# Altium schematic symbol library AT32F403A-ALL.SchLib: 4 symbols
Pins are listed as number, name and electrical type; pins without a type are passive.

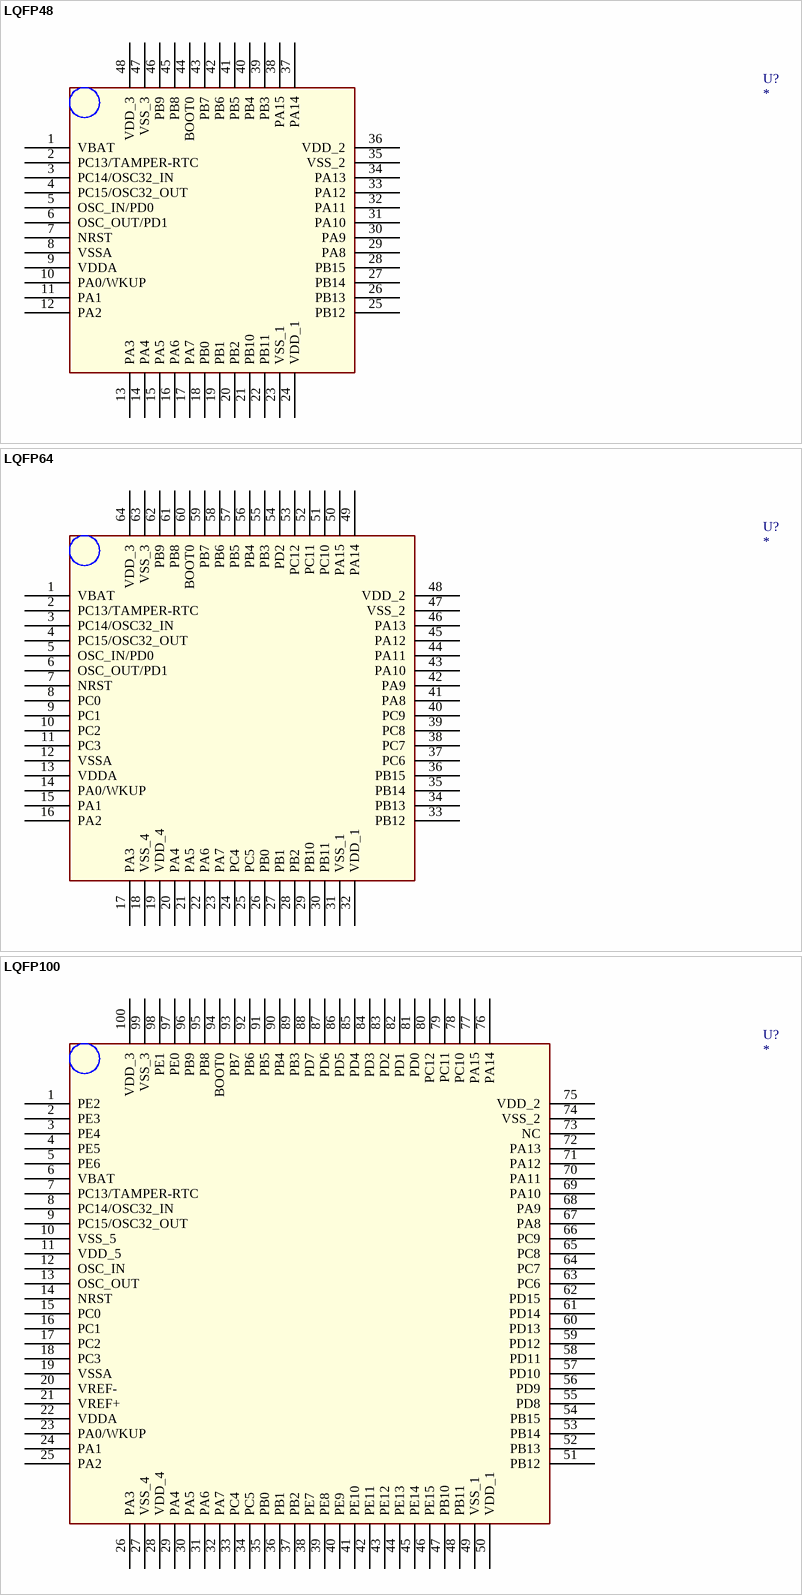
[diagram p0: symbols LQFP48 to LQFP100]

## LQFP48
designator U?
pins: 1 VBAT, 2 PC13/TAMPER-RTC, 3 PC14/OSC32_IN, 4 PC15/OSC32_OUT, 5 OSC_IN/PD0, 6 OSC_OUT/PD1, 7 NRST, 8 VSSA, 9 VDDA, 10 PA0/WKUP, 11 PA1, 12 PA2, 13 PA3, 14 PA4, 15 PA5, 16 PA6, 17 PA7, 18 PB0, 19 PB1, 20 PB2, 21 PB10, 22 PB11, 23 VSS_1, 24 VDD_1, 25 PB12, 26 PB13, 27 PB14, 28 PB15, 29 PA8, 30 PA9, 31 PA10, 32 PA11, 33 PA12, 34 PA13, 35 VSS_2, 36 VDD_2, 37 PA14, 38 PA15, 39 PB3, 40 PB4, 41 PB5, 42 PB6, 43 PB7, 44 BOOT0, 45 PB8, 46 PB9, 47 VSS_3, 48 VDD_3

## LQFP64
designator U?
pins: 1 VBAT, 2 PC13/TAMPER-RTC, 3 PC14/OSC32_IN, 4 PC15/OSC32_OUT, 5 OSC_IN/PD0, 6 OSC_OUT/PD1, 7 NRST, 8 PC0, 9 PC1, 10 PC2, 11 PC3, 12 VSSA, 13 VDDA, 14 PA0/WKUP, 15 PA1, 16 PA2, 17 PA3, 18 VSS_4, 19 VDD_4, 20 PA4, 21 PA5, 22 PA6, 23 PA7, 24 PC4, 25 PC5, 26 PB0, 27 PB1, 28 PB2, 29 PB10, 30 PB11, 31 VSS_1, 32 VDD_1, 33 PB12, 34 PB13, 35 PB14, 36 PB15, 37 PC6, 38 PC7, 39 PC8, 40 PC9, 41 PA8, 42 PA9, 43 PA10, 44 PA11, 45 PA12, 46 PA13, 47 VSS_2, 48 VDD_2, 49 PA14, 50 PA15, 51 PC10, 52 PC11, 53 PC12, 54 PD2, 55 PB3, 56 PB4, 57 PB5, 58 PB6, 59 PB7, 60 BOOT0, 61 PB8, 62 PB9, 63 VSS_3, 64 VDD_3

## LQFP100
designator U?
pins: 1 PE2, 2 PE3, 3 PE4, 4 PE5, 5 PE6, 6 VBAT, 7 PC13/TAMPER-RTC, 8 PC14/OSC32_IN, 9 PC15/OSC32_OUT, 10 VSS_5, 11 VDD_5, 12 OSC_IN, 13 OSC_OUT, 14 NRST, 15 PC0, 16 PC1, 17 PC2, 18 PC3, 19 VSSA, 20 VREF-, 21 VREF+, 22 VDDA, 23 PA0/WKUP, 24 PA1, 25 PA2, 26 PA3, 27 VSS_4, 28 VDD_4, 29 PA4, 30 PA5, 31 PA6, 32 PA7, 33 PC4, 34 PC5, 35 PB0, 36 PB1, 37 PB2, 38 PE7, 39 PE8, 40 PE9, 41 PE10, 42 PE11, 43 PE12, 44 PE13, 45 PE14, 46 PE15, 47 PB10, 48 PB11, 49 VSS_1, 50 VDD_1, 51 PB12, 52 PB13, 53 PB14, 54 PB15, 55 PD8, 56 PD9, 57 PD10, 58 PD11, 59 PD12, 60 PD13, 61 PD14, 62 PD15, 63 PC6, 64 PC7, 65 PC8, 66 PC9, 67 PA8, 68 PA9, 69 PA10, 70 PA11, 71 PA12, 72 PA13, 73 NC, 74 VSS_2, 75 VDD_2, 76 PA14, 77 PA15, 78 PC10, 79 PC11, 80 PC12, 81 PD0, 82 PD1, 83 PD2, 84 PD3, 85 PD4, 86 PD5, 87 PD6, 88 PD7, 89 PB3, 90 PB4, 91 PB5, 92 PB6, 93 PB7, 94 BOOT0, 95 PB8, 96 PB9, 97 PE0, 98 PE1, 99 VSS_3, 100 VDD_3

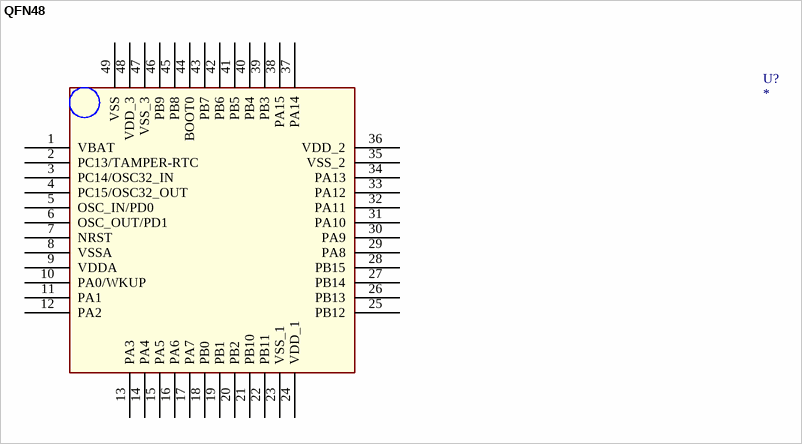
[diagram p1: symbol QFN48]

## QFN48
designator U?
pins: 1 VBAT, 2 PC13/TAMPER-RTC, 3 PC14/OSC32_IN, 4 PC15/OSC32_OUT, 5 OSC_IN/PD0, 6 OSC_OUT/PD1, 7 NRST, 8 VSSA, 9 VDDA, 10 PA0/WKUP, 11 PA1, 12 PA2, 13 PA3, 14 PA4, 15 PA5, 16 PA6, 17 PA7, 18 PB0, 19 PB1, 20 PB2, 21 PB10, 22 PB11, 23 VSS_1, 24 VDD_1, 25 PB12, 26 PB13, 27 PB14, 28 PB15, 29 PA8, 30 PA9, 31 PA10, 32 PA11, 33 PA12, 34 PA13, 35 VSS_2, 36 VDD_2, 37 PA14, 38 PA15, 39 PB3, 40 PB4, 41 PB5, 42 PB6, 43 PB7, 44 BOOT0, 45 PB8, 46 PB9, 47 VSS_3, 48 VDD_3, 49 VSS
